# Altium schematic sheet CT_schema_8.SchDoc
size 484 x 335 mm
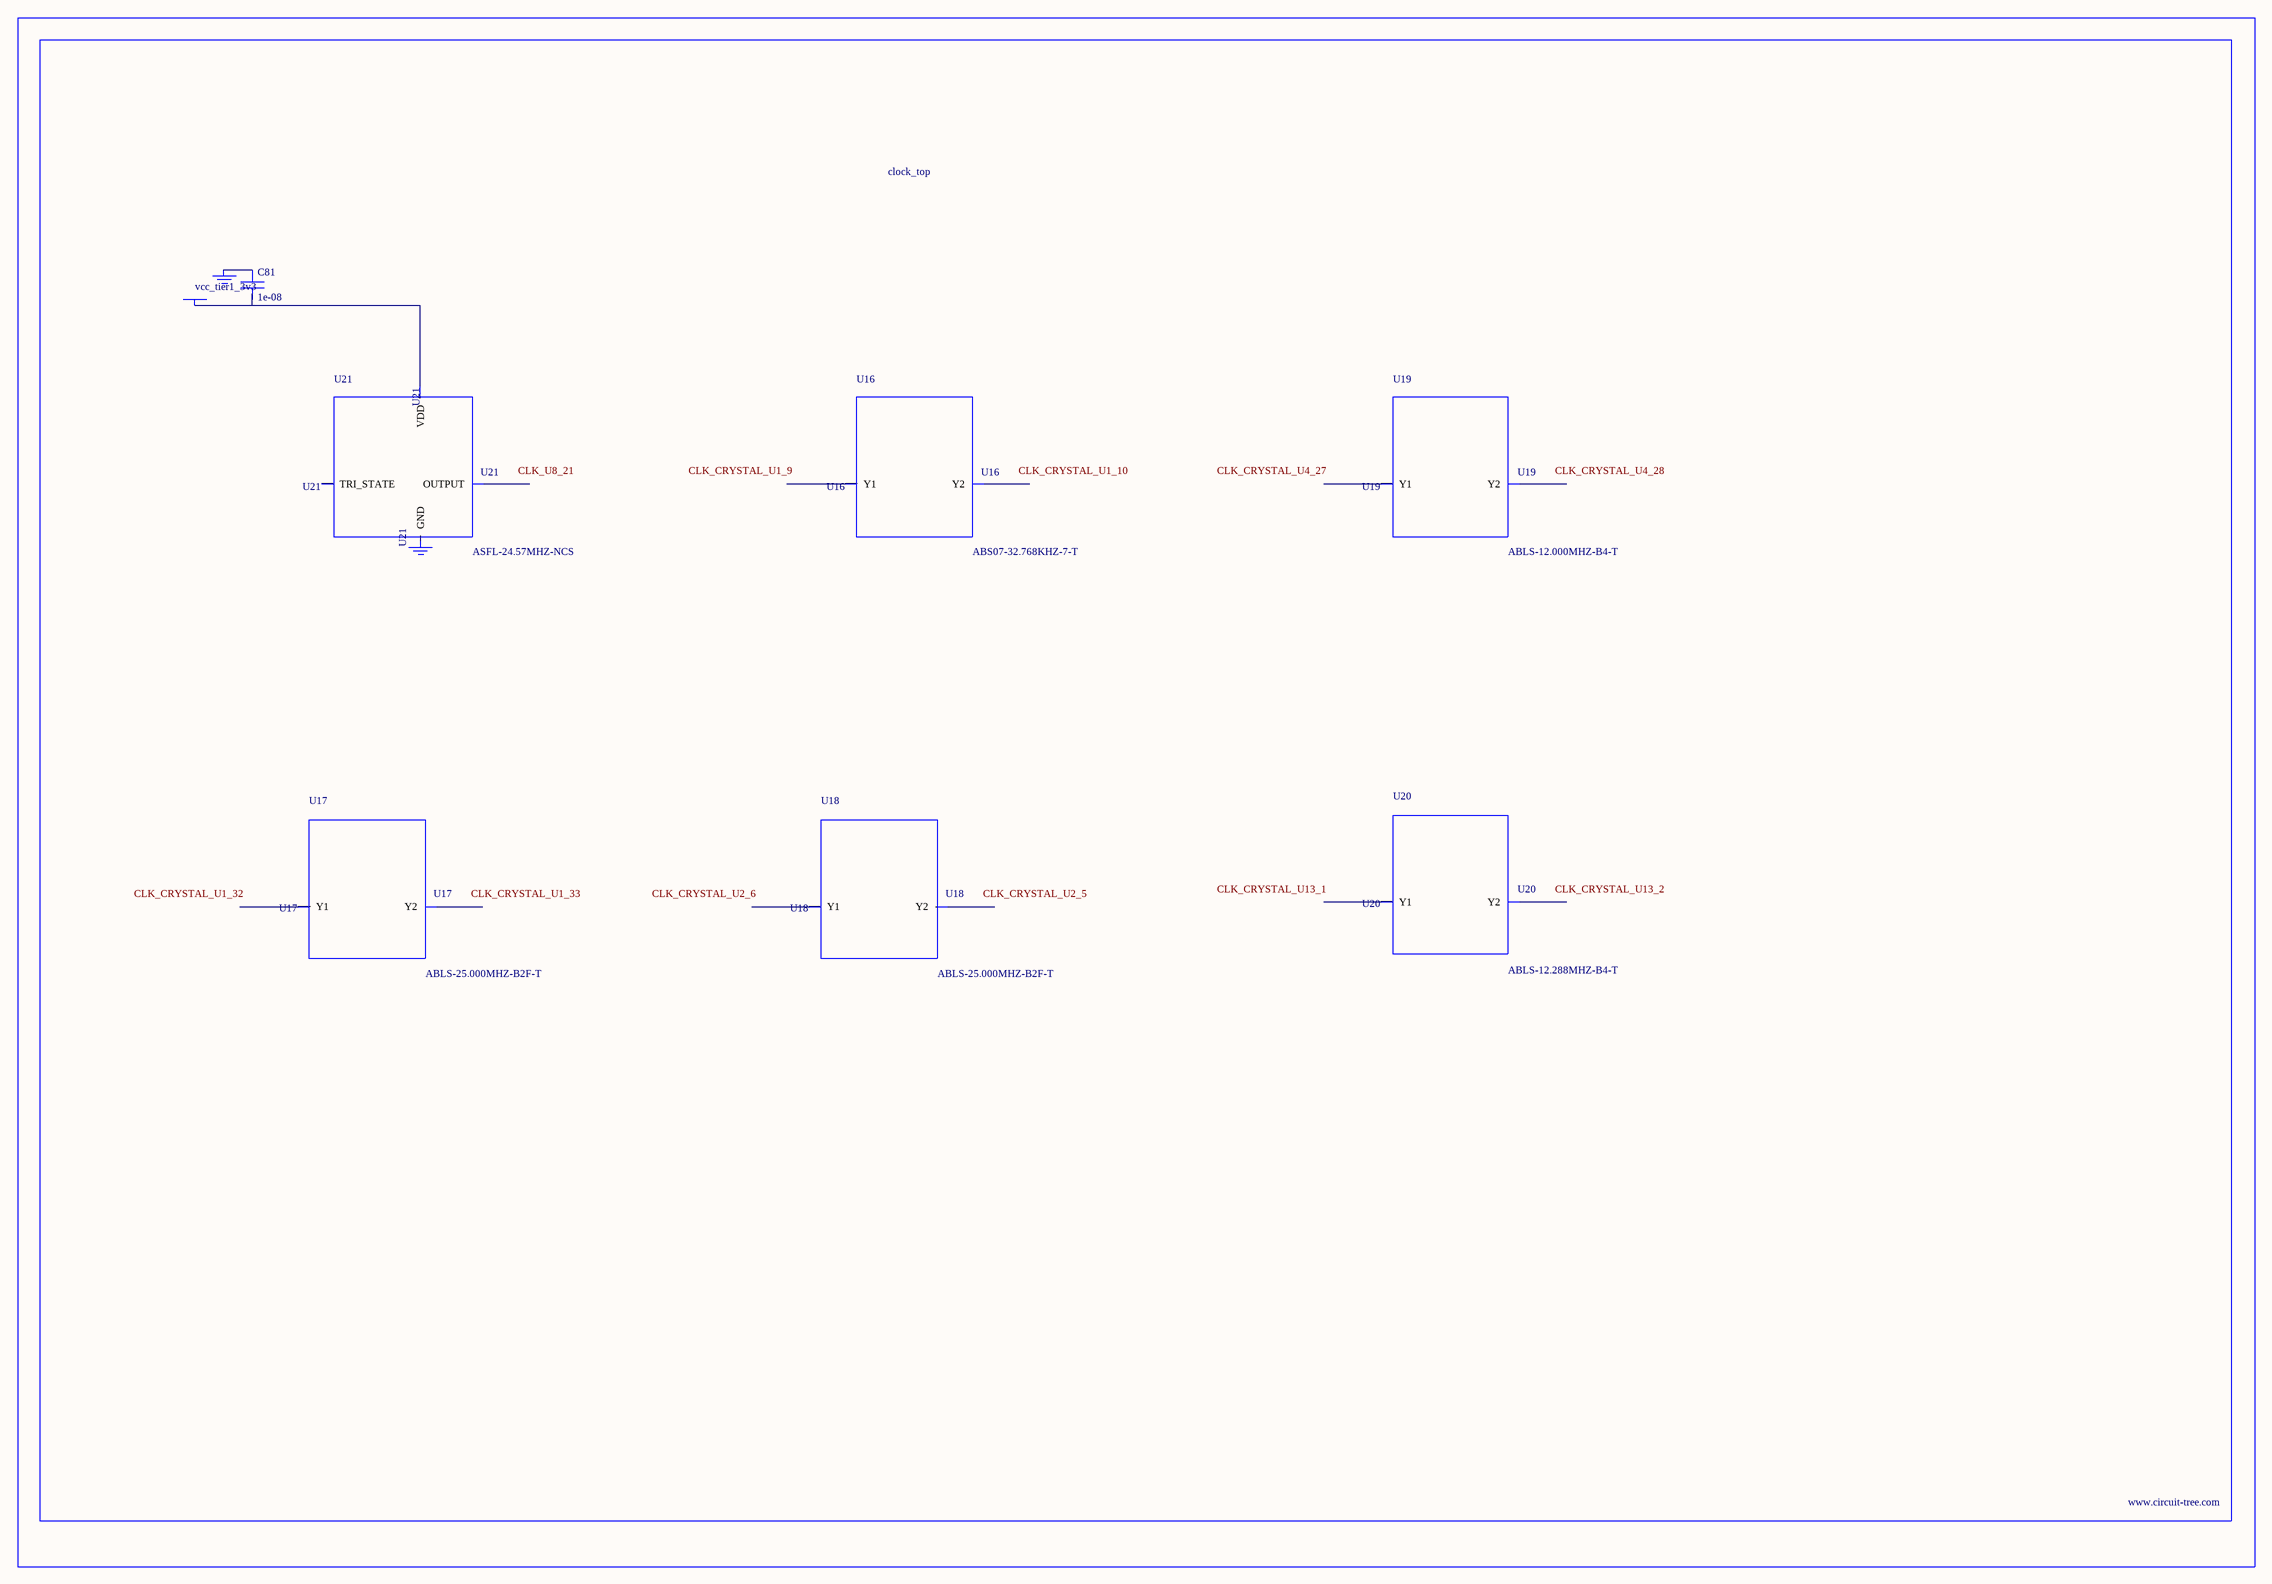
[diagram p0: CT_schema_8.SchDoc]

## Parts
BORDER7  (no value)
C81  1e-08  [C0402]
GND_INSTANCE_7_0  (no value)
GND_INSTANCE_7_1  (no value)
POWER_INSTANCE_7_0  vcc_tier1_3v3
U16  ABS07-32.768KHZ-7-T  [ABS07-32.768KHZ-7-T]
U17  ABLS-25.000MHZ-B2F-T  [ABLS-25.000MHZ-B2F-T]
U18  ABLS-25.000MHZ-B2F-T  [ABLS-25.000MHZ-B2F-T]
U19  ABLS-12.000MHZ-B4-T  [ABLS-12.000MHZ-B4-T]
U20  ABLS-12.288MHZ-B4-T  [ABLS-12.288MHZ-B4-T]
U21  ASFL-24.57MHZ-NCS  [ASFL1]

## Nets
NetC81_1: C81.1 GND_INSTANCE_7_0.0(GND)
NetC81_2: C81.2 POWER_INSTANCE_7_0.0(PWR) U21.4(VDD)

Not connected (* = marked no-connect by the designer): GND_INSTANCE_7_1 0(GND); U16 1(Y1) 2(Y2); U17 1(Y1) 2(Y2); U18 1(Y1) 2(Y2); U19 1(Y1) 2(Y2); U20 1(Y1) 2(Y2); U21 1(TRI_STATE) 2(GND) 3(OUTPUT)

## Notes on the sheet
- Labels drawn without touching a wire or pin: CLK_CRYSTAL_U1_9, CLK_CRYSTAL_U1_10, CLK_CRYSTAL_U1_32, CLK_CRYSTAL_U1_33, CLK_CRYSTAL_U2_5, CLK_CRYSTAL_U2_6, CLK_CRYSTAL_U4_27, CLK_CRYSTAL_U4_28, CLK_CRYSTAL_U13_1, CLK_CRYSTAL_U13_2, CLK_U8_21

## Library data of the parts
BORDER7 = BORDER_PAGE7
C81 = C0402C103K3RAC
GND_INSTANCE_7_0 GND_INSTANCE_7_1 = GND
POWER_INSTANCE_7_0 = PWR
